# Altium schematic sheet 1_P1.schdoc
size 309 x 223 mm; Symbol: Sheet-Symbol_A4; Device: Sheet-Symbol_A4; @Page Name: P1; @Create Date: 2023-05-20; @Page Count: 1; @Page No: 1; @Project Name: 基于STM32的红外热成像; @Schematic Name: Schematic1; @Update Date: 2023-09-20; Company: 嘉立创EDA; Page Size: A4; Version: V1.0
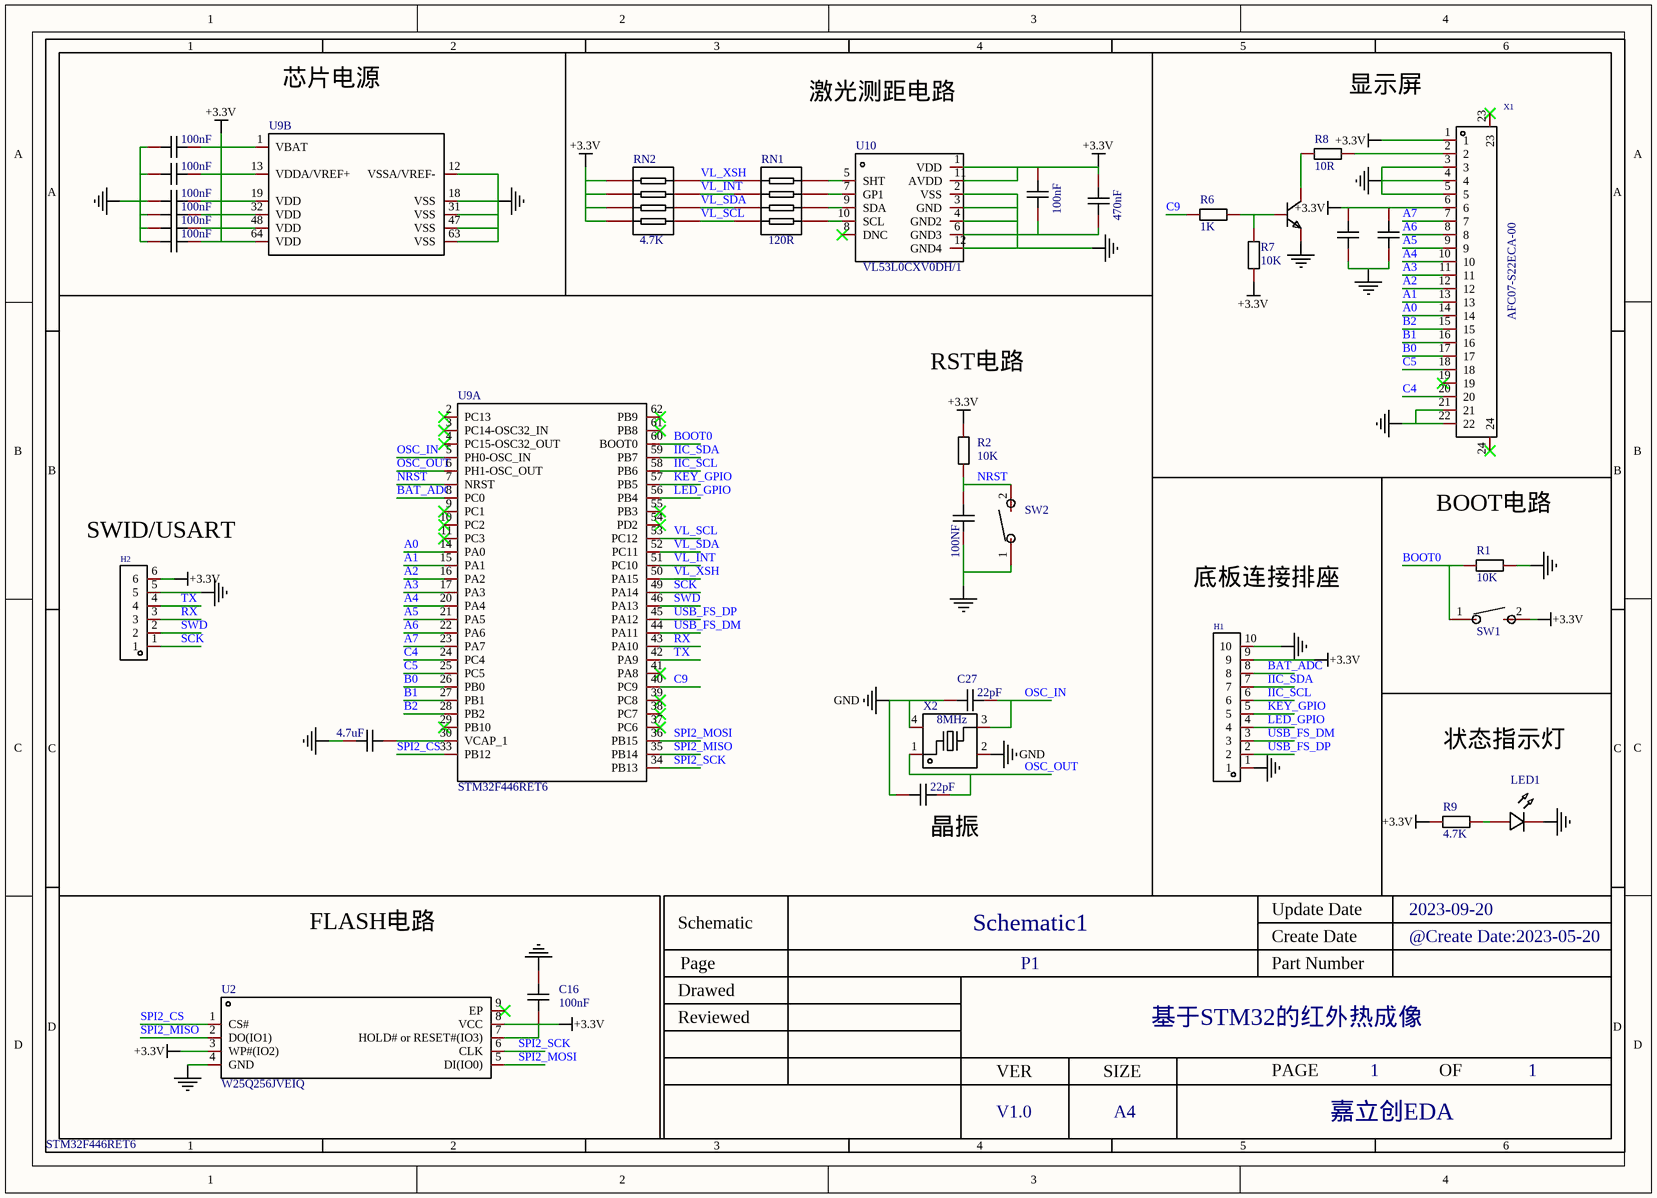
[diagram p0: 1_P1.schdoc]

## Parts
C2  100nF  [C0603]  (value not drawn)
C3  100nF  [C0603]  (value not drawn)
C16  100nF  [C0603]
C17  100nF  [C0603]
C18  100nF  [C0603]
C19  100nF  [C0603]
C20  100nF  [C0603]
C21  100nF  [C0603]
C22  100nF  [C0603]
C23  4.7uF  [C0603]
C24  100NF  [C0603]
C25  100nF  [C0603]
C26  470nF  [C0603]
C27  22pF  [C0603]
C28  22pF  [C0603]
H1  KH-1.27PH180-1X10P-L7.2  [HDR-TH_10P-P1.27-V-M]  (value not drawn)
H2  HDR-F_2.54_1x6P  [HDR-TH_6P-P2.54-V-F]  (value not drawn)
LED1  LED_0603-R  [LED_0603]  (value not drawn)
Q1  SS8050  [SOT-23-3_L2.9-W1.3-P1.90-LS2.4-BR]  (value not drawn)
R1  10K  [R0603]
R2  10K  [R0603]
R6  1K  [R0603]
R7  10K  [R0603]
R8  10R  [R0603]
R9  4.7K  [R0603]
RN1  120R  [RES-ARRAY-SMD_0603-8P-L3.2-W1.6-BL]
RN2  4.7K  [RES-ARRAY-SMD_0603-8P-L3.2-W1.6-BL]
SW1  TSA363G25-250B  [SW-SMD_L6.1-W3.6-LS8.0]  (value not drawn)
SW2  TSA363G25-250B  [SW-SMD_L6.1-W3.6-LS8.0]  (value not drawn)
U2  W25Q256JVEIQ  [WSON-8_L6.0-W8.0-P1.27-BL-EP]
U9  STM32F446RET6  [LQFP-64_L10.0-W10.0-P0.50-LS12.0-BL]  (parts A,B of 2)
U10  VL53L0CXV0DH/1  [OPTO-SMD_12P_VL53L0CXV0DH-1]
X1  AFC07-S22ECA-00  [FPC-SMD_AFC07-S22ECA-00]
X2  8MHz  [CRYSTAL-SMD_4P-L3.2-W2.5-BL]

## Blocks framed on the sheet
芯片电源: C17-C22 U9
激光测距电路: C25 C26 RN1 RN2 U10
显示屏: C2 C3 Q1 R6-R8 X1
底板连接排座: H1
BOOT电路: R1 SW1
状态指示灯: LED1 R9
FLASH电路: C16 U2

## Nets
+3.3V: C2.2 C3.2 C16.1 C17.2 C18.2 C19.2 C20.2 C21.2 C22.2 C25.2 C26.2 H1.9 H2.6 R2.1 R7.1 R9.1 RN2.1 RN2.2 RN2.3 RN2.4 SW1.2 U2.3(WP#(IO2)) U2.7(HOLD#_or_RESET#(IO3)) U2.8(VCC) U9.1(VBAT) U9.13(VDDA/VREF+) U9.19(VDD) U9.32(VDD) U9.48(VDD) U9.64(VDD) U10.1(VDD) U10.11(AVDD) X1.1 X1.6
GND: C27.1 C28.1 X2.2(GND) X2.4(GND)
NetC2_1: C2.1 C3.1 C16.2 C17.1 C18.1 C19.1 C20.1 C21.1 C22.1 C23.1 C24.1 C25.1 C26.1 H1.1 H1.10 H2.5 LED1.1(C) Q1.2(E) R1.2 SW2.1 U2.4(GND) U9.12(VSSA/VREF-) U9.18(VSS) U9.31(VSS) U9.47(VSS) U9.63(VSS) U10.2(VSS) U10.3(GND) U10.4(GND2) U10.6(GND3) U10.12(GND4) X1.3 X1.4 X1.5 X1.21 X1.22
A0: U9.14(PA0) X1.14
A1: U9.15(PA1) X1.13
A2: U9.16(PA2) X1.12
A3: U9.17(PA3) X1.11
A4: U9.20(PA4) X1.10
A5: U9.21(PA5) X1.9
A6: U9.22(PA6) X1.8
A7: U9.23(PA7) X1.7
B0: U9.26(PB0) X1.17
B1: U9.27(PB1) X1.16
B2: U9.28(PB2) X1.15
BAT_ADC: H1.8 U9.8(PC0)
BOOT0: R1.1 SW1.1 U9.60(BOOT0)
C4: U9.24(PC4) X1.20
C5: U9.25(PC5) X1.18
C9: R6.1 U9.40(PC9)
IIC_SCL: H1.6 U9.58(PB6)
IIC_SDA: H1.7 U9.59(PB7)
KEY_GPIO: H1.5 U9.57(PB5)
LED_GPIO: H1.4 U9.56(PB4)
NRST: C24.2 R2.2 SW2.2 U9.7(NRST)
OSC_IN: C27.2 U9.5(PH0-OSC_IN) X2.3
OSC_OUT: C28.2 U9.6(PH1-OSC_OUT) X2.1
RX: H2.3 U9.43(PA10)
SCK: H2.1 U9.49(PA14)
SPI2_CS: U2.1(CS#) U9.33(PB12)
SPI2_MISO: U2.2(DO(IO1)) U9.35(PB14)
SPI2_MOSI: U2.5(DI(IO0)) U9.36(PB15)
SPI2_SCK: U2.6(CLK) U9.34(PB13)
SWD: H2.2 U9.46(PA13)
TX: H2.4 U9.42(PA9)
USB_FS_DM: H1.3 U9.44(PA11)
USB_FS_DP: H1.2 U9.45(PA12)
VL_INT: RN1.2 RN2.7 U9.51(PC10)
VL_SCL: RN1.4 RN2.5 U9.53(PC12)
VL_SDA: RN1.3 RN2.6 U9.52(PC11)
VL_XSH: RN1.1 RN2.8 U9.50(PA15)
NetC23_2: C23.2 U9.30(VCAP_1)
NetLED1_2: LED1.2(A) R9.2
NetQ1_1: Q1.1(B) R6.2 R7.2
NetQ1_3: Q1.3(C) R8.2
NetR8_1: R8.1 X1.2
NetRN1_5: RN1.5 U10.10(SCL)
NetRN1_6: RN1.6 U10.9(SDA)
NetRN1_7: RN1.7 U10.7(GP1)
NetRN1_8: RN1.8 U10.5(SHT)

Not connected (* = marked no-connect by the designer): U2 9(EP)*; U9 2(PC13)* 3(PC14-OSC32_IN)* 4(PC15-OSC32_OUT)* 9(PC1)* 10(PC2)* 11(PC3)* 29(PB10)* 37(PC6)* 38(PC7)* 39(PC8)* 41(PA8)* 54(PD2)* 55(PB3)* 61(PB8)* 62(PB9)*; U10 8(DNC)*; X1 19* 23* 24*

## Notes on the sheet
- RST电路
- (near H2) SWID/USART
- (near C28) 晶振

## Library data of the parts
C2 C3 C16-C28 = CAP_0603: Symbol: CapAcitance; Convert to PCB: yes
H1 = KH-1.27PH180-1X10P-L7.2: 排数:单排;总PIN位数:10P;间距:1.27mm;插针结构:1x10P;行距:-;安装类型:直插;圆针/方针:方针;额定电流:1A;额定电压:-;配合针长度:3.9mm;塑高:1mm;端接针长度:2.3mm;工作温度范围:-40℃~+105℃;颜色:-;; Manufacturer: kinghelm(金航标); Add into BOM: yes; Pitch: 1.27mm; Pin Structure: 1x10P; Circluar Pins/Square Pins: 方针; Current Rating (Max): 1A
H2 = HDR-F_2.54_1x6P: Manufacturer: BOOMELE(博穆精密); Manufacturer Part: 2.54-1*6P母; Symbol: Header-Female-2.54_1x6; Convert to PCB: yes
LED1 = LED_0603-R: Symbol: LED_R; Convert to PCB: yes
Q1 = SS8050_C2150: 晶体管类型:NPN;集射极击穿电压(Vceo):25V;集电极电流(Ic):1.5A;功率(Pd):300mW;直流电流增益(hFE@Ic,Vce):200@100mA,1V;; Manufacturer: CJ(江苏长电/长晶); Add into BOM: yes; Transistor Type: NPN; Collector-Emitter Breakdown Voltage (Vceo): 25V; Collector Current (Ic): 1.5A; Power Dissipation (Pd): 300mW; Collector Cut-Off Current (Icbo): 100nA; Collector-Emitter Saturation Voltage (VCE(sat)@Ic,Ib): 500mV@800mA,80mA; Transition Frequency (fT): 100MHz
R1 R2 R6-R9 = Res_0603: Symbol: 电阻; Convert to PCB: yes
RN1 RN2 = 4D03WGJ0103T5E: 阻值:10kΩ;精度:±5%;单个元件功率:62.5mW;电阻器数:4;; Manufacturer: UNI-ROYAL(厚声); Add into BOM: yes; Tolerance: ±5%; Power(Watts): 62.5mW; Number of Resistors: 4; Temperature Coefficient: ±200ppm/℃
SW1 SW2 = TSA363G25-250B: 触点电流:50mA;额定电压(DC):12V;绝缘电阻:100MΩ;电路结构:单刀单掷;安装方式:立贴;带灯:无;作用力:250gf@±50gf;机械寿命:5万次;带支架:否;; Manufacturer: BRIGHT(博瑞泰); Add into BOM: yes; Contact Current: 50mA; Voltage Rating (DC): 12V; Insulation Resistance: 100MΩ; Circuit: 单刀单掷; Actuator Style: 矩形按钮; Actuator/Cap Color: 白色; With Lamp: 无; Mechanical Life: 5万次; Pin Style: 鸥翼型; Switch Length: 6.05mm; Switch Width: 3.6mm; Switch Height: 2.5mm; Strike Gundam: 否
U2 = W25Q256JVEIQ: Manufacturer: WINBOND(华邦); Add into BOM: yes
U9 = STM32F446RET6: CPU内核:ARM Cortex-M4;CPU最大主频:180MHz;程序存储容量:512KB;程序存储器类型:FLASH;RAM总容量:128KB;GPIO端口数量:50;; Manufacturer: ST(意法半导体); Add into BOM: yes; CPU Maximum Speed: 180MHz; Operating Voltage Range: 1.7V~3.6V; Program Storage Size: 512KB; Program Memory Type: FLASH; RAM Size: 128KB; GPIO Ports Number: 50; ADC (Bit): 12bit; Universal Serial Bus: 有; Peripheral/Function: PWM；PWM；低电压检测
U10 = VL53L0CXV0DH/1: TOF  激光 测距 高精度 传感器 超小体积; Manufacturer: ST(意法半导体); Add into BOM: yes
X1 = AFC07-S22ECA-00: 间距:0.5mm;触点数量:22;锁定特性:抽屉式;安装类型:卧贴;触点类型:上接;工作温度范围:-;; Manufacturer: JS(钜硕电子); Add into BOM: yes; Pitch: 0.5mm; Number of Contacts: 22; Locking Feature: 抽屉式; FFC, FCB Thickness: 0.3mm~0.3mm
X2 = 3225-8.00-12-10-10/A: 频率:8MHz;频率公差:±10ppm;频率稳定度:±10ppm;负载电容:12pF;; Manufacturer: LIMING(利明); Add into BOM: yes; Crystal Type: 贴片无源晶振; Frequency Tolerance: ±10ppm; Load Capacitance: 12pF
